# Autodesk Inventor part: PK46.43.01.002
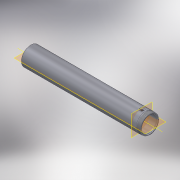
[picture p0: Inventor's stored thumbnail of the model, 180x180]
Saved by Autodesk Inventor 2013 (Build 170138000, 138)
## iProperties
Shininess: 64.0
Length Units: 11269
Angle Units: 11279
Time Units: 11290
Mass Units: 11283
Length Display Precision: 3
Angle Display Precision: 2
Compacted: True
Part Number: PK46.43.01.002
Document SubType Name: Modeling
Created: 2004-11
Material: Сталь высокопрочная низколегированная
Designer: ELarisa
Manufacturer: Standard
Standards Organization: Custom
Density: 7.84 g/cm^3
Density: 0.0
Volumn: 0.0
Area: 0.0
PropertySet Name: Model Information
Control State: 0
Master: False
Checked Out: False
Checked Out Date: 2008-10-09
Last Check In Date: 2008-10-09
Author: ELarisa
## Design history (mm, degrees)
sketch "Эскиз1"
  geometry: L1 (-897.858, -57.258)-(-897.858, 6.242); L2 (-897.858, 6.242)-(-893.308, 18.742); L3 (-893.308, 18.742)-(30.142, 18.742); L4 (30.142, 18.742)-(30.142, 16.242); L5 (30.142, 16.242)-(35.142, 16.242); L6 (35.142, 16.242)-(36.642, 17.742); L7 (36.642, 17.742)-(63.142, 17.742); L8 (63.142, 17.742)-(65.142, 15.742); L9 (65.142, 15.742)-(65.142, -57.258); L10 (65.142, -57.258)-(-897.858, -57.258); L11 (-897.858, 5.242)-(53.142, 5.242); L12 (53.142, 5.242)-(58.142, 6.582); L13 (58.142, 6.582)-(58.142, 9.742); L14 (58.142, 9.742)-(65.142, 9.742)
  constraints: 28 end point, 6 parallel, 3 perpendicular, 2 point on line, 1 vertical
  dimensions: "d0" = 963 distance of L9.end L1.start; "d3" = 5 horizontal distance of L11.end L12.end; "d4" = 76 distance between parallel lines of L10 L3; "d5" = 75 distance between parallel lines of L10 L7; "d6" = 135 deg angle of L7 L6; "d7" = 135 deg angle of L8 L7 (derived); "d8" = 2 horizontal distance of L7.end L8.end; "d9" = 5 distance of L4.end L5.end; "d10" = 35 distance between parallel lines of L4 L9; "d11" = 1.5 distance from line of L6.end L5; "d12" = 62.5 distance between parallel lines of L10 L11; "d13" = 7 distance of L13.end L14.end; "d14" = 165 deg angle of L12 L11; "d15" = 67 distance between parallel lines of L10 L14; "d17" = 63.5 distance of L1.start L1.end; "d18" = 20 deg angle of L2 L1
revolve "Вращение1" sketch "Эскиз1" stored, may be unused: angle "d19" = 90 deg
feature "Резьба1" dims "d20" = 10, "d21" = 0
node "РабОсь1"
node "РабПлоскость1"
sketch "Эскиз2"
  geometry: L1 (-1090.458, -57.258)-(257.742, -57.258) reference; L2 (65.142, -124.258)-(65.142, 9.742) reference; 1 further point
  dimensions: "d23" = 0 distance from line of L1 point (3.142, -57.258); "d24" = 62 distance from line of L2 point (3.142, -57.258)
hole "Отверстие1" sketch "Эскиз2" diameter "d25" = 20; stored, may be unused: countersink angle "d29" = 82 deg, drill point angle "d31" = 118 deg; dims "d26" = 6, "d27" = 36, "d28" = 5, "d30" = 20
body "Solid1"
other parameters: "d22" = 76
